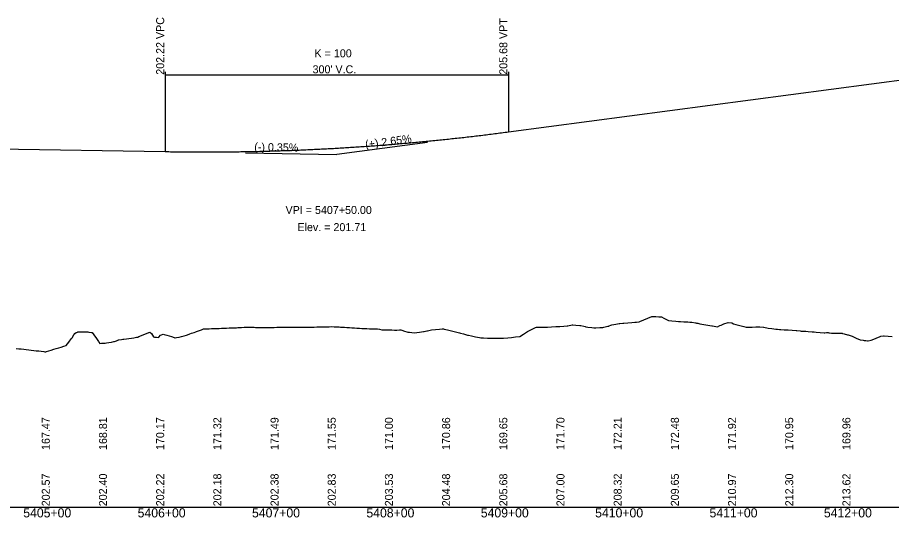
# Model space of a CAD drawing. Extents: x 1876258 to 1932803, y 754739 to 837911.
# Drawn here: x 1878452 to 1879217, y 775980 to 776418 of the extents above; entities that cross this region are included whole.
import ezdxf

# ---------------------------------------------------------------- set-up
doc = ezdxf.new("R2010")
doc.units = 0
for name, color, linetype in [('RD_DDB_GradeTX', 7, 'Continuous'), ('RD_DDB_Profile_EX', 7, 'Continuous'), ('RD_DDB_Profile_Lbl', 7, 'Continuous'), ('RD_DDB_Profile_PR', 7, 'Continuous'), ('RD_DDB_StaTX', 7, 'Continuous'), ('RD_DDB_StripGrade', 7, 'Continuous'), ('RD_DDB_VCLbl', 7, 'Continuous'), ('RD_GPK_Profile_Cell', 7, 'Continuous')]:
    doc.layers.add(name, color=color, linetype=linetype)

msp = doc.modelspace()

# ---------------------------------------------------------------- linework, layer by layer
at = {"layer": 'RD_DDB_GradeTX'}
for p in [(1878810.93, 776308.17), (1878651.64, 776299.05)]:
    msp.add_line(p, (1878731.62, 776297.67), dxfattribs=at)
at = {"layer": 'RD_DDB_Profile_EX'}
for points in [[(1878781.94, 776144.12), (1878783.62, 776144.1), (1878784.13, 776144.11), (1878786.32, 776144.15), (1878787.54, 776144.17), (1878788.51, 776143.88), (1878790.7, 776143.21), (1878792.89, 776142.54), (1878793.63, 776142.32), (1878795.08, 776142.16), (1878797.27, 776141.93), (1878799.62, 776141.68), (1878801.65, 776141.98), (1878803.84, 776142.31), (1878807.34, 776142.84), (1878808.05, 776142.95), (1878810.25, 776143.36), (1878810.85, 776143.49), (1878814.48, 776144.24), (1878817.85, 776144.61), (1878821.35, 776144.98), (1878823.61, 776145.22), (1878824.52, 776145.17), (1878824.86, 776145.09), (1878825.41, 776144.98), (1878828.36, 776144.25), (1878831.86, 776143.39), (1878835.36, 776142.54), (1878838.86, 776141.69), (1878839.78, 776141.47), (1878842.37, 776140.74), (1878845.87, 776139.76), (1878846.78, 776139.51), (1878849.37, 776138.96), (1878852.87, 776138.22), (1878856.37, 776137.49), (1878857.52, 776137.25), (1878859.02, 776137.25), (1878859.45, 776137.24), (1878859.88, 776137.23), (1878863.38, 776137.14), (1878866.88, 776137.06), (1878870.38, 776136.98), (1878873.89, 776136.9), (1878874.64, 776136.88), (1878877.39, 776137.12), (1878881.17, 776137.32), (1878884.39, 776137.68), (1878887.89, 776138.08), (1878891.65, 776138.5), (1878894.9, 776140.53), (1878898.4, 776142.69), (1878901.9, 776144.45), (1878905.41, 776146.2), (1878906.24, 776146.62), (1878908.91, 776146.61), (1878912.41, 776146.6), (1878914.27, 776146.6), (1878915.91, 776146.7), (1878919.41, 776146.91), (1878922.92, 776147.13), (1878926.42, 776147.34), (1878929.92, 776147.56), (1878932.97, 776147.74), (1878933.42, 776147.85), (1878937.21, 776148.73), (1878937.83, 776148.71), (1878940.43, 776148.48), (1878943.93, 776148.16), (1878945.01, 776148.07), (1878947.43, 776147.49), (1878948.64, 776147.2), (1878949.4, 776146.98), (1878950.93, 776146.7), (1878954.44, 776146.33), (1878956.39, 776146.13), (1878957.94, 776145.93), (1878961.44, 776146.26), (1878961.81, 776146.3), (1878964.17, 776146.47), (1878964.94, 776146.72), (1878968.44, 776147.42), (1878969.48, 776147.63), (1878969.82, 776147.79), (1878971.23, 776148.41), (1878971.95, 776148.56), (1878975.45, 776149.27), (1878978.52, 776149.9), (1878978.95, 776149.94), (1878981.76, 776150.21), (1878982.45, 776150.26), (1878985.96, 776150.53), (1878989.46, 776150.8), (1878992.25, 776151.02), (1878992.96, 776151.07), (1878993.49, 776151.1), (1878995.78, 776151.34), (1878996.46, 776151.62), (1878999.96, 776153.05), (1879003.47, 776154.47), (1879006.97, 776155.89)], [(1879006.97, 776155.89), (1879007.33, 776156.04), (1879010.47, 776155.88), (1879013.14, 776155.74), (1879013.97, 776155.69), (1879015.32, 776155.6), (1879017.48, 776154.57), (1879020.98, 776152.89), (1879021.66, 776152.56), (1879024.48, 776152.25), (1879027.98, 776151.87), (1879030.31, 776151.62), (1879031.48, 776151.57), (1879031.97, 776151.55), (1879034.99, 776151.39), (1879038.49, 776151.19), (1879040.24, 776151.1), (1879041.99, 776150.88), (1879045.06, 776150.51), (1879045.49, 776150.37), (1879046.07, 776150.19), (1879047.09, 776150.02), (1879048.99, 776149.68), (1879050.79, 776149.35), (1879052.5, 776149.06), (1879056, 776148.46), (1879059.5, 776147.87), (1879059.94, 776147.8), (1879063, 776147.22), (1879064.32, 776146.97), (1879066.51, 776148.04), (1879067.48, 776148.51), (1879070.01, 776149.42), (1879073.67, 776150.73), (1879077.01, 776150.37), (1879078.32, 776149.58), (1879080.51, 776149.02), (1879084.02, 776148.12), (1879087.52, 776147.21), (1879089.35, 776146.74), (1879091.02, 776146.72), (1879094.65, 776146.66), (1879098.03, 776146.81), (1879100.85, 776146.94), (1879101.53, 776146.87), (1879104.48, 776146.6), (1879105.03, 776146.5), (1879108.72, 776145.82), (1879112.03, 776145.4), (1879115.54, 776144.97), (1879116.87, 776144.8), (1879118.6, 776144.59), (1879119.04, 776144.55), (1879119.68, 776144.5), (1879122.79, 776144.32), (1879126.04, 776144.16), (1879129.54, 776144), (1879133.05, 776143.83), (1879133.76, 776143.79), (1879136.55, 776143.32), (1879137.64, 776143.13), (1879140.05, 776143.11), (1879141.71, 776143), (1879143.59, 776142.94), (1879147.06, 776142.59), (1879147.42, 776142.55), (1879149.01, 776142.45), (1879150.56, 776142.34), (1879154.06, 776142.08), (1879157.56, 776141.81), (1879158.18, 776141.77), (1879159.79, 776141.88), (1879161.06, 776141.83), (1879161.62, 776141.76), (1879162.3, 776141.75), (1879164.09, 776141.47), (1879164.57, 776141.47), (1879168.07, 776141.45), (1879168.56, 776141.44), (1879171.57, 776141.31), (1879173.39, 776141.25), (1879173.73, 776141.22), (1879175.07, 776140.84), (1879177.94, 776140.03), (1879178.58, 776139.89), (1879179.41, 776139.72), (1879182.08, 776138.78), (1879185.58, 776137.1), (1879189.08, 776135.49), (1879191.88, 776135.17), (1879192.58, 776135.05), (1879193.2, 776134.95), (1879194.05, 776134.82), (1879195.65, 776134.73), (1879196.09, 776134.81), (1879198.78, 776135.28), (1879199.59, 776135.61), (1879203.09, 776137.04), (1879206.59, 776138.47), (1879207.16, 776138.7), (1879209.57, 776138.96)], [(1878451.26, 776128.01), (1878453.45, 776127.77), (1878455.64, 776127.52), (1878457.83, 776127.27), (1878460.02, 776127.03), (1878462.21, 776126.78), (1878464.4, 776126.53), (1878466.59, 776126.29), (1878468.78, 776126.04), (1878470.97, 776125.79), (1878473.16, 776125.54), (1878475.35, 776125.29), (1878476.38, 776125.17), (1878477.06, 776125.1), (1878477.65, 776125.31), (1878479.73, 776125.94), (1878481.92, 776126.6), (1878484.11, 776127.26), (1878486.3, 776127.91), (1878488.49, 776128.57), (1878490.68, 776129.23), (1878492.87, 776129.89), (1878495.06, 776130.59), (1878497.25, 776133.43), (1878499.44, 776136.27), (1878500.23, 776137.29), (1878501.63, 776139.83), (1878502.38, 776141.19), (1878503.82, 776141.85), (1878504.86, 776142.33), (1878505.23, 776142.52), (1878506.01, 776142.52), (1878506.81, 776142.51), (1878508.2, 776142.5), (1878510.39, 776142.48), (1878512.58, 776142.46), (1878513.3, 776142.45), (1878513.94, 776142.44), (1878514.77, 776142.34), (1878517.18, 776142.04), (1878517.79, 776141.83), (1878519.15, 776139.86), (1878521.34, 776136.67), (1878523.12, 776134.08), (1878523.53, 776133.58), (1878524.5, 776132.39), (1878525.72, 776132.49), (1878527.91, 776132.67), (1878528.95, 776132.76), (1878530.1, 776132.94), (1878532.29, 776133.29), (1878534.48, 776133.63), (1878536.67, 776133.98), (1878537.33, 776134.08), (1878538.86, 776134.71), (1878540.73, 776135.48), (1878541.05, 776135.52), (1878543.24, 776135.81), (1878544.62, 776135.99), (1878545.01, 776136.02), (1878545.43, 776136.08), (1878547.62, 776136.42), (1878549.81, 776136.75), (1878552, 776137.08), (1878554.19, 776137.42), (1878556.38, 776137.75), (1878557.49, 776137.92), (1878558.57, 776138.36), (1878560.76, 776139.25), (1878562.95, 776140.15), (1878565.14, 776141.05), (1878567.33, 776141.95), (1878568.22, 776142.28), (1878569.52, 776141.06), (1878571.17, 776138.22), (1878571.71, 776138.04), (1878572.06, 776137.92), (1878573.9, 776137.75), (1878575.7, 776137.59), (1878576.09, 776138.01), (1878577.5, 776139.53), (1878578.28, 776139.87), (1878579.8, 776140.5), (1878580.47, 776140.32), (1878582.93, 776139.66), (1878584.85, 776139.05), (1878587.04, 776138.35), (1878589.23, 776137.64), (1878590.05, 776137.38), (1878590.37, 776137.28), (1878591.42, 776137.46), (1878593.61, 776137.84), (1878595.8, 776138.49), (1878597.99, 776139.12), (1878600.18, 776139.75), (1878602.37, 776140.45), (1878603.12, 776140.69), (1878604.56, 776141.24)], [(1878604.56, 776141.24), (1878606.75, 776142.08), (1878608.24, 776142.63), (1878608.94, 776142.86), (1878611.38, 776143.62), (1878613.32, 776144.42), (1878614.92, 776145.06), (1878615.51, 776145.09), (1878617.7, 776145.17), (1878619.89, 776145.26), (1878622.08, 776145.34), (1878624.27, 776145.42), (1878626.46, 776145.51), (1878628.81, 776145.59), (1878630.84, 776145.68), (1878633.03, 776145.78), (1878634.5, 776145.85), (1878635.22, 776145.88), (1878637.41, 776145.95), (1878639.6, 776146.03), (1878641.79, 776146.11), (1878643.98, 776146.18), (1878645.02, 776146.22), (1878646.17, 776146.27), (1878648.36, 776146.38), (1878650.55, 776146.49), (1878652.74, 776146.59), (1878654.17, 776146.66), (1878654.93, 776146.63), (1878657.12, 776146.57), (1878659.31, 776146.5), (1878660.48, 776146.47), (1878661.5, 776146.45), (1878662.12, 776146.45), (1878663.69, 776146.43), (1878665.88, 776146.4), (1878668.07, 776146.38), (1878670.26, 776146.35), (1878672.72, 776146.32), (1878674.64, 776146.39), (1878676.83, 776146.47), (1878679.02, 776146.54), (1878679.83, 776146.57), (1878681.21, 776146.6), (1878683.4, 776146.64), (1878685.59, 776146.68), (1878687.78, 776146.71), (1878689.28, 776146.74), (1878689.97, 776146.74), (1878692.16, 776146.72), (1878694.35, 776146.71), (1878696.54, 776146.69), (1878698.73, 776146.68), (1878700.92, 776146.66), (1878703.11, 776146.65), (1878705.3, 776146.63), (1878707.09, 776146.62), (1878707.72, 776146.64), (1878708.52, 776146.66), (1878709.68, 776146.7), (1878711.87, 776146.76), (1878714.06, 776146.83), (1878714.94, 776146.86), (1878716.25, 776146.85), (1878718.44, 776146.85), (1878720.63, 776146.85), (1878721.56, 776146.85), (1878722.02, 776146.85), (1878722.82, 776146.89), (1878725.01, 776146.99), (1878727.2, 776147.07), (1878729.38, 776146.97), (1878730.82, 776146.91), (1878731.57, 776146.88), (1878733.76, 776146.78), (1878734.9, 776146.73), (1878735.95, 776146.66), (1878738.14, 776146.53), (1878740.33, 776146.39), (1878742.52, 776146.25), (1878744.71, 776146.12), (1878746.9, 776145.98), (1878749.09, 776145.85), (1878751.28, 776145.71), (1878753.47, 776145.58), (1878754.59, 776145.51), (1878755.66, 776145.47), (1878757.85, 776145.38), (1878760.04, 776145.3), (1878762.23, 776145.21), (1878764.42, 776145.13), (1878766.61, 776145.05), (1878767.08, 776145.03), (1878768.8, 776144.76), (1878770.99, 776144.43), (1878771.79, 776144.3), (1878773.18, 776144.28), (1878775.37, 776144.24), (1878777.56, 776144.2), (1878779.75, 776144.16), (1878781.94, 776144.12)], [(1879209.57, 776138.96), (1879210.09, 776138.93), (1879213.6, 776138.75), (1879217.1, 776138.57)]]:
    msp.add_lwpolyline(points, dxfattribs=at)
at = {"layer": 'RD_DDB_Profile_PR'}
for p, q in [((1878881.62, 776317.53), (1879616.62, 776414.82)), ((1878266.62, 776305.7), (1878581.62, 776300.26))]:
    msp.add_line(p, q, dxfattribs=at)
msp.add_spline([(1878581.62, 776300.26), (1878587.62, 776300.17), (1878593.62, 776300.09), (1878599.62, 776300.03), (1878605.62, 776299.99), (1878611.62, 776299.97), (1878617.62, 776299.96), (1878623.62, 776299.98), (1878629.62, 776300.01), (1878635.62, 776300.06), (1878641.62, 776300.12), (1878647.62, 776300.21), (1878653.62, 776300.31), (1878659.62, 776300.43), (1878665.62, 776300.57), (1878671.62, 776300.73), (1878677.62, 776300.9), (1878683.62, 776301.1), (1878689.62, 776301.31), (1878695.62, 776301.53), (1878701.62, 776301.78), (1878707.62, 776302.05), (1878713.62, 776302.33), (1878719.62, 776302.63), (1878725.62, 776302.95), (1878731.62, 776303.28), (1878737.62, 776303.64), (1878743.62, 776304.01), (1878749.62, 776304.4), (1878755.62, 776304.81), (1878761.62, 776305.23), (1878767.62, 776305.68), (1878773.62, 776306.14), (1878779.62, 776306.62), (1878785.62, 776307.12), (1878791.62, 776307.63), (1878797.62, 776308.17), (1878803.62, 776308.72), (1878809.62, 776309.29), (1878815.62, 776309.88), (1878821.62, 776310.48), (1878827.62, 776311.11), (1878833.62, 776311.75), (1878839.62, 776312.41), (1878845.62, 776313.09), (1878851.62, 776313.78), (1878857.62, 776314.49), (1878863.62, 776315.23), (1878869.62, 776315.98), (1878875.62, 776316.74), (1878881.62, 776317.53)], degree=3, dxfattribs=at)
at = {"layer": 'RD_DDB_VCLbl'}
for p, q in [((1878581.62, 776370.03), (1878581.62, 776300.26)), ((1878881.62, 776370.03), (1878881.62, 776317.53)), ((1878581.62, 776367.53), (1878881.62, 776367.53))]:
    msp.add_line(p, q, dxfattribs=at)
at = {"layer": 'RD_GPK_Profile_Cell'}
msp.add_line((1877681.62, 775989.14), (1883481.62, 775989.14), dxfattribs=at)

# ---------------------------------------------------------------- texts
at = {"layer": 'RD_DDB_GradeTX'}
for s, rotation, p in [('(-) 0.35%', 359.0112, (1878659.35, 776300.92)), ('(+) 2.65%', 7.54051, (1878756.81, 776303.02))]:
    msp.add_text(s, height=7, rotation=rotation, dxfattribs=at).set_placement(p)
at = {"layer": 'RD_DDB_Profile_Lbl'}
for s, p in [('VPI = 5407+50.00', (1878686.72, 776245.67)), ('Elev. = 201.71', (1878697.15, 776230.67))]:
    msp.add_text(s, height=7, dxfattribs=at).set_placement(p)
at = {"layer": 'RD_DDB_StaTX'}
for s, p in [('5405+00', (1878457.42, 775980.14)), ('5406+00', (1878557.42, 775980.14)), ('5407+00', (1878657.42, 775980.14)), ('5408+00', (1878757.42, 775980.14)), ('5409+00', (1878857.42, 775980.14)), ('5410+00', (1878957.42, 775980.14)), ('5411+00', (1879057.42, 775980.14)), ('5412+00', (1879157.42, 775980.14))]:
    msp.add_text(s, height=8, dxfattribs=at).set_placement(p)
at = {"layer": 'RD_DDB_StripGrade'}
for s, p in [('202.22 VPC', (1878580.62, 776367.53)), ('205.68 VPT', (1878880.62, 776367.53)), ('167.47', (1878480.62, 776039.14)), ('168.81', (1878530.62, 776039.14)), ('170.17', (1878580.62, 776039.14)), ('171.32', (1878630.62, 776039.14)), ('171.49', (1878680.62, 776039.14)), ('171.55', (1878730.62, 776039.14)), ('171.00', (1878780.62, 776039.14)), ('170.86', (1878830.62, 776039.14)), ('169.65', (1878880.62, 776039.14)), ('171.70', (1878930.62, 776039.14)), ('172.21', (1878980.62, 776039.14)), ('172.48', (1879030.62, 776039.14)), ('171.92', (1879080.62, 776039.14)), ('170.95', (1879130.62, 776039.14)), ('169.96', (1879180.62, 776039.14)), ('202.57', (1878480.62, 775989.89)), ('202.40', (1878530.62, 775989.89)), ('202.22', (1878580.62, 775989.89)), ('202.18', (1878630.62, 775989.89)), ('202.38', (1878680.62, 775989.89)), ('202.83', (1878730.62, 775989.89)), ('203.53', (1878780.62, 775989.89)), ('204.48', (1878830.62, 775989.89)), ('205.68', (1878880.62, 775989.89)), ('207.00', (1878930.62, 775989.89)), ('208.32', (1878980.62, 775989.89)), ('209.65', (1879030.62, 775989.89)), ('210.97', (1879080.62, 775989.89)), ('212.30', (1879130.62, 775989.89)), ('213.62', (1879180.62, 775989.89))]:
    msp.add_text(s, height=7, rotation=90, dxfattribs=at).set_placement(p)
at = {"layer": 'RD_DDB_VCLbl'}
for s, p in [('K = 100', (1878712.07, 776382.78)), ("300' V.C.", (1878710.37, 776368.78))]:
    msp.add_text(s, height=7, dxfattribs=at).set_placement(p)

doc.saveas('drawing.dxf')
